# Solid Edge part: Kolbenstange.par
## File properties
Username: ahadarics
Dokumentum tartalom típus: 0
Author: ahadarics
Last saved by: ahadarics
Revision: 82
Sűrűség: 0,000 kg/m^3
Pontosság: 0,990
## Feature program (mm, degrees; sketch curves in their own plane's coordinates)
base feature "unnamed BaseFeature 1"
thread "unnamed Thread 1"
chamfer "Letörés_1" setback 0.7
sketch for "Kihúzás_1" plane through (57.5, 0, 0) normal (1, 0, 0) x-axis (0, 1, 0)
  circle centre (0, 0) radius 12.5
extrude "Kihúzás_1" add finite 27 along -normal
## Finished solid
Body 1: solid body, 13 faces, 23 edges, 12 vertices.
  Faces by surface: plane 9, cylinder 3, cone 1
  Edges by curve: line 12, circle 11
Bounding box of the edges (mm): 254.500 x 25.000 x 25.000, from (-197, -12.5, -12.5) to (57.5, 12.5, 12.5).
Cylindrical faces by radius (mm): R5 x2, R12.5 x1
Conical faces (half-angle, radius in mm at the cone's reference point): 45 deg R4.3 x1
Planar faces by outward normal: +x 3, +z 1, -x 4, -z 1
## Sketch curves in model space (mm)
circle centre (57.5, 0, 0) radius 12.5
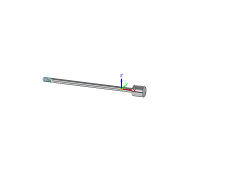
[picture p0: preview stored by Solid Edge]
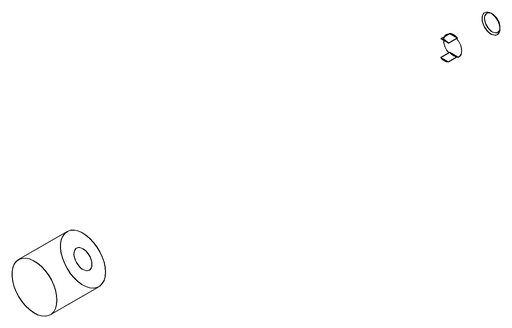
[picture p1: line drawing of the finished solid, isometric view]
